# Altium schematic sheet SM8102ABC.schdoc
size 127 x 101 mm
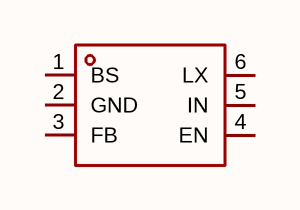
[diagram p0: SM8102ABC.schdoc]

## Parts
U?  sm8102abc  [SOT-23-6_L2.9-W1.6-P0.95-LS2.8-BR]  (value not drawn)

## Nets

Not connected (* = marked no-connect by the designer): U? 1(BS) 2(GND) 3(FB) 4(EN) 5(IN) 6(LX)

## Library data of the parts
U? = sm8102abc: 功能类型:降压型;工作电压:4.2V~18V;输出电压:-;输出电流:2A;输出类型:可调;; Manufacturer: Silergy(矽力杰); AddInBom: yes; ModelId: 18da8f6c14a34920b3e136b5c401a119; ModelName: SOT-23-6_L2.9-W1.6-H1.5-LS2.8-P0.95; ModelTransform: 110.73671,114.173,0,180,0,0,0.001,-0.003,0; Function: 降压型; Output Current: 2A; Frequency - Switching: 500kHz; Synchronous Rectifier: 是; Number of Outputs: 1; Topology: 降压式; Quiescent Current: 250uA; Switch tube (built-in/external): 内置; Output Type: 可调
